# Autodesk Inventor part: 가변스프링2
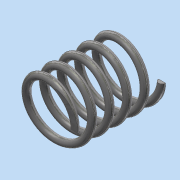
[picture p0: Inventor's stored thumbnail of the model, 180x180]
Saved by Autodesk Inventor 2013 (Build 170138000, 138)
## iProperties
Created: 2018-10
Part Number: 가변스프링2
Material: 스테인리스강
Document SubType Name: Modeling
Designer: Administrator
Density: 8.08 g/cm^3
Mass: 6.26491 g
Surface Area: 15.7543 cm^2
Volume: 0.775361 cm^3
Author: Administrator
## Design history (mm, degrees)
sketch "스케치1"
  geometry: L1 (0, 0)-(0, 24.744); L2 (0, 0)-(8, 0); L3 (0, 24.744)-(8, 24.744); C1 r 1 at (8, 0)
  constraints: 6 end point, 1 centre point, 1 coincident, 1 parallel, 1 perpendicular, 1 vertical
  dimensions: "d0" = 24.74445 distance of L1.start L1.end (derived); "d3" = 8 distance of L1.start L2.end; "d4" = 2 diameter of C1; "d5" = 8 distance of L1.end L3.end
feature "코일1" sketch "스케치1" pitch "d6" = 10; turns "d8" = 5; dims "d7" = 24.74445 (= d0), "d9" = 0, angle "d10" = 90 deg, angle "d11" = 90 deg, "d12" = 0, "d13" = 0
sketch "스케치2"
  geometry: L1 (24.744, 10)-(0, 10); L2 (0, 10)-(0, -10); L3 (0, -10)-(24.744, -10); L4 (24.744, -10)-(24.744, 10); 2 further points
  constraints: 8 end point, 2 parallel, 1 coincident, 1 horizontal, 1 midpoint, 1 perpendicular
  dimensions: "d14" = 24.74445 distance of L2.end L3.end (derived); "d16" = 20 distance of L3.end L1.start
extrude "돌출1" sketch "스케치2" stored distance "d17" = 0; taper "d18" = 0 deg
node "솔리드1"
